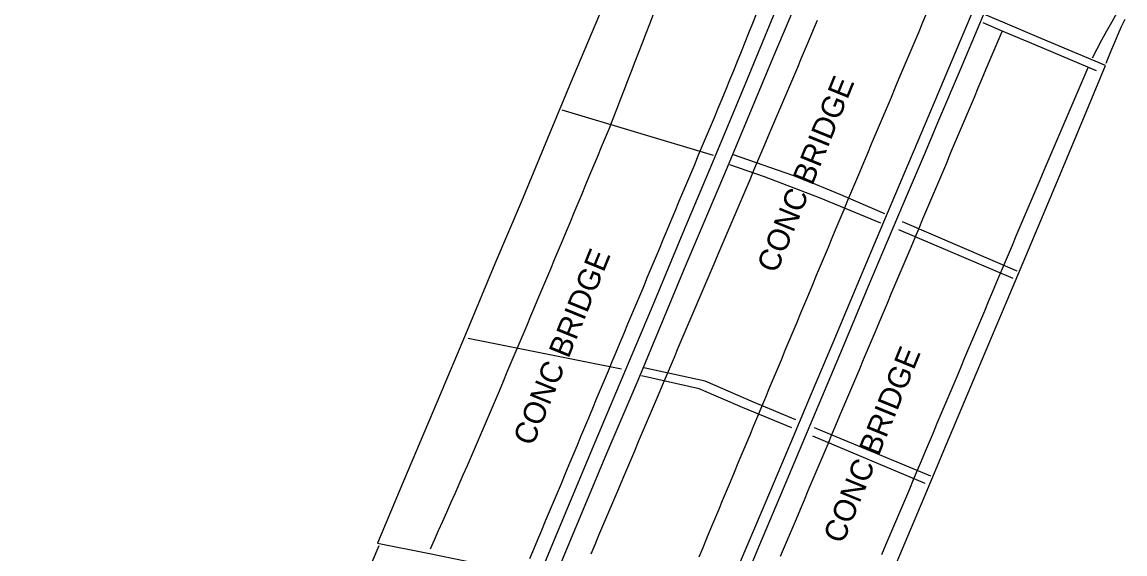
# Model space of a CAD drawing. Extents: x 1948091 to 1975253, y 787267 to 823306.
# Drawn here: x 1968860 to 1969131, y 797826.1 to 797956.8 of the extents above; entities that cross this region are included whole.
import ezdxf

# ---------------------------------------------------------------- set-up
doc = ezdxf.new("R2010")
doc.units = 0
for name, color, linetype in [('RD_EX_Bridge', 7, 'Continuous'), ('RD_EX_Bridge_Seam', 7, 'Continuous'), ('RD_EX_Pavement_Markings', 7, 'Continuous'), ('RD_EX_Road', 7, 'Continuous'), ('RD_TX_RoadID', 7, 'Continuous')]:
    doc.layers.add(name, color=color, linetype=linetype)

msp = doc.modelspace()

# ---------------------------------------------------------------- linework, layer by layer
at = {"layer": 'RD_EX_Bridge'}
for points in [[(1969054.38, 797971.42), (1969044.46, 797948), (1969033.28, 797921.01), (1969022.73, 797896.14), (1969011.29, 797868.71), (1969003.49, 797850.4), (1968992.11, 797823.09)], [(1969005.77, 797967.95), (1969000.97, 797956.53), (1968995.36, 797943.19), (1968989.13, 797928.16), (1968982.62, 797912.52), (1968976.21, 797897.38), (1968969.36, 797881.01), (1968961.93, 797863.32), (1968953.72, 797844), (1968947.32, 797828.79), (1968959.74, 797826.29), (1968972.52, 797823.68), (1968982.52, 797821.71), (1968987.11, 797820.75), (1968987.22, 797821.01), (1968992.91, 797834.57), (1969000.86, 797853.58), (1969006.81, 797867.76), (1969015.04, 797887.31), (1969022.46, 797905.07), (1969030.14, 797923.33), (1969037.72, 797941.42), (1969045.24, 797959.71)], [(1969036.52, 797824.24), (1969041.67, 797836.39), (1969045.77, 797846.05), (1969049.53, 797854.99), (1969053.96, 797865.52), (1969059.28, 797878.08), (1969064.15, 797889.6), (1969069.29, 797901.84), (1969076.24, 797918.3), (1969080.19, 797927.63), (1969085.11, 797939.22), (1969091.28, 797953.82), (1969093.98, 797960.2)], [(1969031.42, 797805.04), (1969037.16, 797802.49), (1969044.59, 797799.19), (1969048.2, 797797.73), (1969057.14, 797794.03), (1969061.35, 797792.33), (1969067.7, 797806.72), (1969072.82, 797819.04), (1969077.64, 797830.45), (1969081.63, 797840.01), (1969087.13, 797853.11), (1969097.54, 797877.69), (1969102.05, 797888.39), (1969107.26, 797900.78), (1969114.43, 797917.76), (1969120.67, 797932.67), (1969126.19, 797946.12), (1969110.43, 797952.74), (1969101.55, 797956.46), (1969096.28, 797958.69)], [(1969096.18, 797958.46), (1969095.33, 797956.46), (1969090.5, 797945.07), (1969085.22, 797932.61), (1969081.64, 797924.15), (1969076.53, 797912.11), (1969071.44, 797900.15), (1969067.84, 797891.62), (1969061.49, 797876.46), (1969054.21, 797859.21), (1969046.98, 797842.09), (1969041.2, 797828.35), (1969032, 797806.4), (1969031.42, 797805.04)]]:
    msp.add_lwpolyline(points, dxfattribs=at)
at = {"layer": 'RD_EX_Bridge_Seam'}
for p, q in [((1968992.66, 797935.23), (1969029.84, 797924.05)), ((1969076.23, 797907.79), (1969104.43, 797895.67)), ((1969103.55, 797893.79), (1969075.4, 797905.75)), ((1969007.32, 797871.54), (1968969.64, 797879.01)), ((1969054.66, 797857.16), (1969083.25, 797845.3)), ((1969081.92, 797843.41), (1969054.27, 797855.06))]:
    msp.add_line(p, q, dxfattribs=at)
for points in [[(1969096.08, 797956.64), (1969100.61, 797954.7), (1969109.03, 797951.14), (1969123.89, 797944.86)], [(1969071.96, 797909.68), (1969061.19, 797914.29), (1969051.24, 797918.42), (1969034.79, 797924.13)], [(1969071.05, 797907.37), (1969055.98, 797913.61), (1969042.47, 797918.74), (1969033.94, 797921.68)], [(1969049.13, 797857.09), (1969037.02, 797862.11), (1969026.36, 797866.63), (1969012.2, 797869.87)], [(1969050.15, 797859.03), (1969039.74, 797863.38), (1969027.86, 797868.55), (1969012.77, 797871.86)]]:
    msp.add_lwpolyline(points, dxfattribs=at)
at = {"layer": 'RD_EX_Pavement_Markings'}
for points in [[(1969082.25, 797958.98), (1969081.28, 797956.68), (1969080.31, 797954.38), (1969079.34, 797952.08), (1969078.37, 797949.78), (1969077.4, 797947.47), (1969076.43, 797945.17), (1969075.46, 797942.87), (1969074.49, 797940.57), (1969073.52, 797938.26), (1969072.55, 797935.96), (1969071.58, 797933.66), (1969070.61, 797931.36), (1969069.64, 797929.06), (1969068.67, 797926.75), (1969067.7, 797924.45), (1969066.73, 797922.15), (1969065.76, 797919.85), (1969064.79, 797917.55), (1969063.82, 797915.24), (1969062.85, 797912.94), (1969061.89, 797910.63), (1969060.93, 797908.33), (1969059.97, 797906.02), (1969059, 797903.72), (1969058.04, 797901.41), (1969057.08, 797899.11), (1969056.12, 797896.8), (1969055.16, 797894.49), (1969054.2, 797892.19), (1969053.23, 797889.88), (1969052.27, 797887.58), (1969051.31, 797885.27), (1969050.35, 797882.96), (1969049.39, 797880.66), (1969048.43, 797878.35), (1969047.46, 797876.05), (1969046.5, 797873.74), (1969045.54, 797871.44), (1969044.58, 797869.13), (1969043.62, 797866.83), (1969042.66, 797864.52), (1969041.69, 797862.22), (1969040.73, 797859.91), (1969039.77, 797857.61), (1969038.81, 797855.3), (1969037.85, 797853), (1969036.88, 797850.69), (1969035.92, 797848.39), (1969034.96, 797846.08), (1969034, 797843.77), (1969033.03, 797841.47), (1969032.07, 797839.16), (1969031.11, 797836.86), (1969030.15, 797834.55), (1969029.19, 797832.25), (1969028.22, 797829.94), (1969027.26, 797827.64), (1969026.3, 797825.33)], [(1969123, 797947.96), (1969124.14, 797950.18), (1969125.28, 797952.4), (1969126.5, 797954.58), (1969127.74, 797956.75), (1969128.98, 797958.92)], [(1969015.09, 797958.62), (1969014.19, 797956.29), (1969013.29, 797953.96), (1969012.39, 797951.62), (1969011.49, 797949.29), (1969010.59, 797946.96), (1969009.69, 797944.63), (1969008.8, 797942.3), (1969007.9, 797939.97), (1969007, 797937.64), (1969006.1, 797935.3), (1969005.2, 797932.97), (1969004.26, 797930.65), (1969003.3, 797928.35), (1969002.34, 797926.04), (1969001.38, 797923.73), (1969000.42, 797921.43), (1968999.46, 797919.12), (1968998.49, 797916.81), (1968997.53, 797914.51), (1968996.57, 797912.2), (1968995.61, 797909.89), (1968994.65, 797907.59), (1968993.69, 797905.28), (1968992.72, 797902.98), (1968991.76, 797900.67), (1968990.79, 797898.37), (1968989.82, 797896.06), (1968988.85, 797893.76), (1968987.89, 797891.46), (1968986.92, 797889.15), (1968985.95, 797886.85), (1968984.98, 797884.54), (1968984.02, 797882.24), (1968983.05, 797879.94), (1968982.08, 797877.63), (1968981.12, 797875.33), (1968980.15, 797873.03), (1968979.17, 797870.73), (1968978.2, 797868.43), (1968977.22, 797866.13), (1968976.25, 797863.83), (1968975.27, 797861.53), (1968974.3, 797859.23), (1968973.32, 797856.93), (1968972.34, 797854.63), (1968971.37, 797852.33), (1968970.38, 797850.03), (1968969.37, 797847.75), (1968968.36, 797845.46), (1968967.35, 797843.18), (1968966.34, 797840.89), (1968965.33, 797838.61), (1968964.32, 797836.33), (1968963.3, 797834.04), (1968962.29, 797831.76), (1968961.28, 797829.47), (1968960.3, 797827.25)], [(1969040.4, 797958.71), (1969039.46, 797956.39), (1969038.53, 797954.07), (1969037.59, 797951.75), (1969036.66, 797949.44), (1969035.73, 797947.12), (1969034.79, 797944.8), (1969033.86, 797942.48), (1969032.92, 797940.17), (1969031.97, 797937.86), (1969031, 797935.55), (1969030.03, 797933.25), (1969029.07, 797930.94), (1969028.1, 797928.64), (1969027.13, 797926.34), (1969026.17, 797924.03), (1969025.2, 797921.73), (1969024.23, 797919.42), (1969023.27, 797917.12), (1969022.31, 797914.81), (1969021.34, 797912.51), (1969020.38, 797910.2), (1969019.41, 797907.9), (1969018.45, 797905.59), (1969017.49, 797903.29), (1969016.52, 797900.98), (1969015.56, 797898.68), (1969014.59, 797896.37), (1969013.63, 797894.07), (1969012.67, 797891.76), (1969011.7, 797889.46), (1969010.74, 797887.15), (1969009.77, 797884.85), (1969008.81, 797882.54), (1969007.85, 797880.24), (1969006.88, 797877.93), (1969005.92, 797875.63), (1969004.96, 797873.32), (1969003.99, 797871.02), (1969003.03, 797868.71), (1969002.07, 797866.41), (1969001.11, 797864.1), (1969000.14, 797861.8), (1968999.18, 797859.49), (1968998.22, 797857.19), (1968997.26, 797854.88), (1968996.29, 797852.58), (1968995.33, 797850.27), (1968994.37, 797847.97), (1968993.41, 797845.66), (1968992.44, 797843.36), (1968991.48, 797841.05), (1968990.52, 797838.75), (1968989.55, 797836.45), (1968988.58, 797834.14), (1968987.61, 797831.84), (1968986.64, 797829.54), (1968985.68, 797827.24), (1968984.71, 797824.94)], [(1969055.37, 797957.12), (1969054.4, 797954.82), (1969053.42, 797952.52), (1969052.45, 797950.22), (1969051.47, 797947.92), (1969050.5, 797945.62), (1969049.52, 797943.32), (1969048.55, 797941.02), (1969047.57, 797938.72), (1969046.6, 797936.42), (1969045.62, 797934.12), (1969044.65, 797931.82), (1969043.67, 797929.52), (1969042.7, 797927.22), (1969041.72, 797924.92), (1969040.75, 797922.62), (1969039.77, 797920.32), (1969038.79, 797918.02), (1969037.81, 797915.72), (1969036.84, 797913.42), (1969035.86, 797911.12), (1969034.88, 797908.82), (1969033.9, 797906.52), (1969032.92, 797904.23), (1969031.94, 797901.93), (1969030.97, 797899.63), (1969029.99, 797897.33), (1969029.01, 797895.03), (1969028.03, 797892.73), (1969027.05, 797890.43), (1969026.08, 797888.13), (1969025.1, 797885.84), (1969024.12, 797883.54), (1969023.14, 797881.24), (1969022.16, 797878.94), (1969021.18, 797876.64), (1969020.21, 797874.34), (1969019.23, 797872.05), (1969018.25, 797869.75), (1969017.28, 797867.45), (1969016.3, 797865.15), (1969015.33, 797862.85), (1969014.36, 797860.55), (1969013.38, 797858.24), (1969012.41, 797855.94), (1969011.43, 797853.64), (1969010.46, 797851.34), (1969009.49, 797849.04), (1969008.51, 797846.74), (1969007.54, 797844.44), (1969006.56, 797842.14), (1969005.59, 797839.84), (1969004.62, 797837.54), (1969003.64, 797835.24), (1969002.67, 797832.94), (1969001.69, 797830.64), (1969000.72, 797828.34), (1968999.75, 797826.04)], [(1969100.71, 797954.36), (1969099.74, 797952.06), (1969098.77, 797949.76), (1969097.79, 797947.46), (1969096.82, 797945.16), (1969095.85, 797942.85), (1969094.88, 797940.55), (1969093.91, 797938.25), (1969092.94, 797935.95), (1969091.97, 797933.65), (1969090.99, 797931.34), (1969090.02, 797929.04), (1969089.05, 797926.74), (1969088.08, 797924.44), (1969087.11, 797922.14), (1969086.14, 797919.84), (1969085.16, 797917.54), (1969084.19, 797915.23), (1969083.22, 797912.93), (1969082.25, 797910.63), (1969081.28, 797908.33), (1969080.31, 797906.03), (1969079.33, 797903.73), (1969078.36, 797901.42), (1969077.39, 797899.12), (1969076.42, 797896.82), (1969075.45, 797894.52), (1969074.48, 797892.22), (1969073.51, 797889.92), (1969072.54, 797887.62), (1969071.56, 797885.32), (1969070.59, 797883.01), (1969069.62, 797880.71), (1969068.65, 797878.41), (1969067.68, 797876.11), (1969066.71, 797873.81), (1969065.74, 797871.51), (1969064.76, 797869.2), (1969063.79, 797866.9), (1969062.82, 797864.6), (1969061.85, 797862.3), (1969060.88, 797860), (1969059.91, 797857.7), (1969058.93, 797855.4), (1969057.96, 797853.09), (1969056.99, 797850.79), (1969056.02, 797848.49), (1969055.05, 797846.19), (1969054.08, 797843.89), (1969053.11, 797841.59), (1969052.14, 797839.29), (1969051.16, 797836.99), (1969050.19, 797834.69), (1969049.22, 797832.38), (1969048.25, 797830.08), (1969047.28, 797827.78), (1969046.31, 797825.48)], [(1969121.84, 797945.55), (1969120.86, 797943.26), (1969119.88, 797940.96), (1969118.9, 797938.66), (1969117.92, 797936.36), (1969116.94, 797934.06), (1969115.97, 797931.76), (1969114.99, 797929.46), (1969114.01, 797927.17), (1969113.03, 797924.87), (1969112.05, 797922.57), (1969111.07, 797920.27), (1969110.09, 797917.97), (1969109.12, 797915.67), (1969108.14, 797913.37), (1969107.16, 797911.08), (1969106.18, 797908.78), (1969105.2, 797906.48), (1969104.22, 797904.18), (1969103.24, 797901.88), (1969102.27, 797899.58), (1969101.3, 797897.28), (1969100.33, 797894.98), (1969099.36, 797892.67), (1969098.39, 797890.37), (1969097.42, 797888.07), (1969096.45, 797885.77), (1969095.48, 797883.47), (1969094.51, 797881.16), (1969093.54, 797878.86), (1969092.57, 797876.56), (1969091.6, 797874.26), (1969090.63, 797871.96), (1969089.66, 797869.65), (1969088.69, 797867.35), (1969087.72, 797865.05), (1969086.75, 797862.75), (1969085.78, 797860.45), (1969084.81, 797858.14), (1969083.84, 797855.84), (1969082.87, 797853.54), (1969081.9, 797851.24), (1969080.93, 797848.94), (1969079.96, 797846.64), (1969078.99, 797844.33), (1969078.02, 797842.03), (1969077.04, 797839.73), (1969076.07, 797837.43), (1969075.1, 797835.13), (1969074.13, 797832.83), (1969073.16, 797830.53), (1969072.18, 797828.23), (1969071.21, 797825.93)]]:
    msp.add_lwpolyline(points, dxfattribs=at)
at = {"layer": 'RD_EX_Road'}
for points in [[(1969130.99, 797957.37), (1969130.09, 797955.56), (1969129.25, 797953.72), (1969128.4, 797951.76), (1969127.44, 797949.44), (1969126.3, 797946.55)], [(1968947.69, 797828.1), (1968944.17, 797819.83), (1968941.25, 797813.68), (1968937.32, 797803.99), (1968933.15, 797793.52), (1968929.58, 797784.84), (1968925.6, 797774.91), (1968921.61, 797766.04), (1968916.66, 797754.8), (1968909.1, 797736.8), (1968901.03, 797717.73), (1968893.59, 797700.18), (1968884.9, 797679.55), (1968875.89, 797657.98), (1968869.36, 797642.71), (1968860.03, 797620.72)]]:
    msp.add_lwpolyline(points, dxfattribs=at)

# ---------------------------------------------------------------- texts
at = {"layer": 'RD_TX_RoadID'}
for p in [(1969045.39, 797894.83), (1968985.5, 797852.38), (1969061.69, 797828.37)]:
    msp.add_text('CONC BRIDGE', height=5.4, rotation=67.8596, dxfattribs=at).set_placement(p)

doc.saveas('drawing.dxf')
